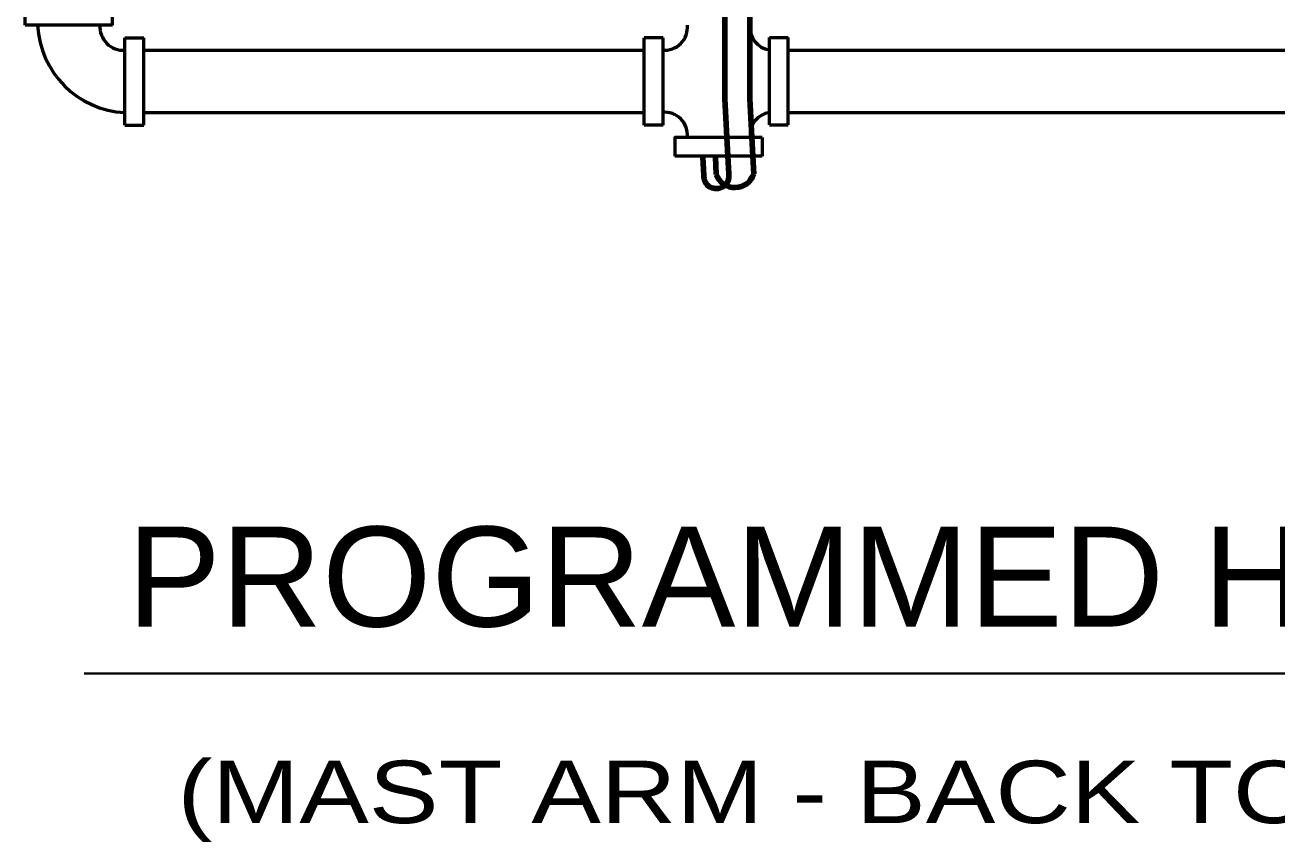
# Model space of a CAD drawing. Extents: x -286 to 394, y -156 to 284.
# Drawn here: x 129.5 to 179.6, y -14.1 to 18.6 of the extents above; entities that cross this region are included whole.
import ezdxf
from ezdxf.enums import TextEntityAlignment as Align

# ---------------------------------------------------------------- set-up
doc = ezdxf.new("R2010")
doc.units = 0
doc.header["$LTSCALE"] = 0.8
doc.layers.add('1', color=7, linetype='Continuous', lineweight=53)

msp = doc.modelspace()

# ---------------------------------------------------------------- linework, layer by layer
at = {"layer": '1', "lineweight": 106}
for p, q in [((157.5446, 36.8315), (157.5446, 15.6258)), ((158.5446, 36.8315), (158.5446, 15.6258)), ((157.5446, 15.6258), (157.6646, 13.3372)), ((156.6658, 13.2848), (156.7029, 12.5776)), ((157.1651, 13.3111), (157.2022, 12.6038)), ((157.6645, 13.3372), (157.7016, 12.6299))]:
    msp.add_line(p, q, dxfattribs=at)
at = {"layer": '1'}
for p, q in [((129.5362, 18.5747), (129.5362, 19.3247)), ((133.0362, 18.5747), (133.0362, 19.3247)), ((133.0362, 18.5747), (129.5362, 18.5747)), ((133.5362, 14.5747), (133.5362, 18.0747)), ((133.5362, 18.0747), (134.2862, 18.0747)), ((134.2862, 14.5747), (134.2862, 18.0747)), ((154.3229, 14.5747), (154.3229, 18.0747)), ((155.0729, 18.0747), (154.3229, 18.0747)), ((155.0729, 14.5747), (155.0729, 18.0747)), ((159.3342, 14.5815), (159.3342, 18.0815)), ((159.3342, 18.0815), (160.0842, 18.0815)), ((160.0842, 14.5815), (160.0842, 18.0815)), ((134.2862, 17.5747), (154.3229, 17.5747)), ((160.0842, 17.5747), (191.0842, 17.5747)), ((134.2862, 15.0747), (154.3229, 15.0747)), ((160.0842, 15.0747), (191.0842, 15.0747)), ((133.5362, 14.5747), (134.2862, 14.5747)), ((155.0729, 14.5747), (154.3229, 14.5747)), ((159.3342, 14.5815), (160.0842, 14.5815)), ((159.0446, 14.0872), (159.0446, 13.3372)), ((159.0446, 13.3372), (155.5446, 13.3372))]:
    msp.add_line(p, q, dxfattribs=at)
at = {"layer": '1', "lineweight": 40}
msp.add_line((131.9092, -7.3701), (197.9471, -7.3701), dxfattribs=at)
at = {"layer": '1', "lineweight": 106}
msp.add_lwpolyline([(158.5446, 15.6258), (158.6645, 13.3372), (158.7016, 12.6299)], dxfattribs=at)
at = {"layer": '1'}
msp.add_lwpolyline([(159.0446, 14.0872), (155.5446, 14.0872), (155.5446, 13.3372)], dxfattribs=at)
for centre, radius, start, end in [((133.7226, 18.7611), 3.6911, 182.89399, 267.10601), ((133.4686, 18.5071), 0.9348, 175.85174, 274.14826), ((155.1436, 18.4825), 0.9064, 263.73087, 6.26912), ((159.4618, 18.4825), 0.9064, 173.73087, 261.91278), ((155.1436, 14.1861), 0.9064, 353.73087, 96.26912), ((159.4618, 14.1861), 0.9064, 98.08722, 186.26913)]:
    msp.add_arc(centre, radius, start, end, dxfattribs=at)
at = {"layer": '1', "lineweight": 106}
for centre, radius, start, end in [((157.2057, 12.5377), 0.5044, 175.46493, 10.53455), ((157.9476, 12.8646), 0.7897, 199.28082, 342.71237)]:
    msp.add_arc(centre, radius, start, end, dxfattribs=at)

# ---------------------------------------------------------------- texts
at = {"layer": '1'}
for s, height, width, p in [('PROGRAMMED HEADS', 4, 1.05, (164.8314, -5.4928)), ('(MAST ARM - BACK TO BACK)', 2.5, 1.25, (165.356, -13.36))]:
    msp.add_text(s, height=height, dxfattribs=dict(at, width=width)).set_placement(p, align=Align.CENTER)

doc.saveas('drawing.dxf')
